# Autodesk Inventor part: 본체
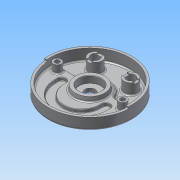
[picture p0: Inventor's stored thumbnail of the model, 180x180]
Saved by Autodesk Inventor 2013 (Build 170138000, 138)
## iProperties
Created: 2015-04
Part Number: 본체
Material: 알루미늄 6061
Document SubType Name: Modeling
Designer: Administrator
Density: 2.71 g/cm^3
Mass: 1041.28 g
Surface Area: 1018.25 cm^2
Volume: 384.235 cm^3
Author: Administrator
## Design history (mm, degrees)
sketch "스케치1"
  geometry: C1 r 95 at (0, 0); 1 further point
  constraints: 1 centre point, 1 coincident
  dimensions: "d0" = 190 diameter of C1
extrude "돌출1" new body sketch "스케치1" stored distance "d1" = 32; taper "d2" = 0 deg
sketch "스케치2"
  geometry: L1 (-90, 0)-(90, 0); L2 (-89.196, 12)-(89.196, 12); A1 r 42 centre (0, 0) between (40.249, 12) and (-40.249, 12); A2 r 90 centre (0, 0) between (89.196, 12) and (-89.196, 12); 3 further points
  constraints: 4 end point, 4 point on circle, 2 centre point, 2 coincident, 2 midpoint, 2 point on line, 1 horizontal, 1 parallel, 1 vertical alignment
  dimensions: "d4" = 12 distance between parallel lines of L2 L1; "d6" = 90 radius of A2; "d7" = 42 radius of A1; "d8" = 178.39282 distance of L2.start L2.end
extrude "돌출2" cut sketch "스케치2" distance "d9" = 25; taper "d10" = 0 deg
fillet "모깎기1" dims "d11" = 10
sketch "스케치3"
  geometry: C1 r 15 at (-40, 52); C2 r 15 at (40, 52); 1 further point
  constraints: 2 centre point
  dimensions: "d12" = 30 diameter of C1; "d13" = 40 horizontal distance of point (0, 0) C1.centre; "d14" = 52 vertical distance of point (0, 0) C1.centre; "d15" = 30 diameter of C2; "d16" = 40 horizontal distance of point (0, 0) C2.centre; "d17" = 52 vertical distance of point (0, 0) C2.centre
extrude "돌출3" join sketch "스케치3" distance "d18" = 25; taper "d19" = 0 deg
hole "구멍1" diameter "d22" = 20; stored, may be unused: countersink angle "d26" = 90 deg, drill point angle "d28" = 118 deg; dims "d20" = 10, "d21" = 10, "d23" = 6, "d24" = 4, "d25" = 2, "d27" = 8
hole "구멍2" diameter "d31" = 20; stored, may be unused: countersink angle "d35" = 90 deg, drill point angle "d37" = 118 deg; dims "d29" = 10, "d30" = 10, "d32" = 6, "d33" = 4, "d34" = 2, "d36" = 8
sketch "스케치4"
  geometry: L1 (-6, 16.431)-(6, 16.431); L2 (6, 16.431)-(6, -16.431); L3 (6, -16.431)-(-6, -16.431); L4 (-6, -16.431)-(-6, 16.431); C1 r 10 at (0, 0) reference; C2 r 15 at (0, 0) reference; 3 further points
  constraints: 8 end point, 2 midpoint, 2 parallel, 1 horizontal, 1 horizontal alignment, 1 perpendicular, 1 vertical alignment
  dimensions: "d38" = 12 distance of L1.start L1.end; "d40" = 32.86237 distance between parallel lines of L3 L1
extrude "돌출4" cut sketch "스케치4" distance "d41" = 3; taper "d42" = 0 deg
sketch "스케치5"
  geometry: L1 (-47.117, 12)-(-76.916, 12) reference; L2 (76.916, 12)-(47.117, 12) reference; L3 (-95, 0)-(95, 0); L4 (0, 0)-(94.638, -8.28); L5 (0, 0)-(-94.638, -8.28); A1 r 42 centre (0, 0) between (38.056, 17.769) and (-38.056, 17.769) reference; A2 r 10 centre (-47.117, 22) between (-47.117, 12) and (-38.056, 17.769) reference; A3 r 10 centre (-76.916, 22) between (-86.53, 24.75) and (-76.916, 12) reference; A4 r 90 centre (0, 0) between (86.53, 24.75) and (-86.53, 24.75) reference; A5 r 10 centre (76.916, 22) between (76.916, 12) and (86.53, 24.75) reference; A6 r 10 centre (47.117, 22) between (38.056, 17.769) and (47.117, 12) reference; A7 r 95 centre (0, 0) between (-95, 0) and (95, 0) reference; A8 r 95 centre (0, 0) between (-94.638, -8.28) and (94.638, -8.28); 2 further points
  constraints: 6 end point, 5 point on circle, 2 coincident, 1 centre point, 1 midpoint, 1 parallel, 2 other
  dimensions: "d44" = 5 deg angle of L3 L4; "d45" = 5 deg angle of L3 L5
extrude "돌출5" cut sketch "스케치5" distance "d46" = 5; taper "d47" = 0 deg
sketch "스케치7"
  geometry: L1 (0, 0)-(94.638, -8.28) reference; L2 (-94.638, -8.28)-(0, 0) reference; L3 (0, 0)-(94.638, -8.28) reference; L4 (-94.638, -8.28)-(0, 0) reference; L5 (-47.117, 12)-(-76.916, 12) reference; L6 (76.916, 12)-(47.117, 12) reference; A1 r 95 centre (0, 0) between (-94.638, -8.28) and (94.638, -8.28) reference; A2 r 95 centre (0, 0) between (94.638, -8.28) and (-94.638, -8.28) reference; A3 r 42 centre (0, 0) between (38.056, 17.769) and (-38.056, 17.769) reference; A4 r 10 centre (-47.117, 22) between (-47.117, 12) and (-38.056, 17.769) reference; A5 r 10 centre (-76.916, 22) between (-86.53, 24.75) and (-76.916, 12) reference; A6 r 90 centre (0, 0) between (86.53, 24.75) and (-86.53, 24.75) reference; A7 r 10 centre (76.916, 22) between (76.916, 12) and (86.53, 24.75) reference; A8 r 10 centre (47.117, 22) between (38.056, 17.769) and (47.117, 12) reference; A9 r 90 centre (0, 0) between (-86.53, 24.75) and (86.53, 24.75); 1 further point
  constraints: 4 point on circle, 1 centre point, 1 coincident, 1 concentric
extrude "돌출6" cut sketch "스케치7" distance "d48" = 18; taper "d49" = 0 deg
sketch "스케치8"
  geometry: C1 r 35 at (0, 0); 1 further point
  constraints: 1 centre point, 1 coincident
  dimensions: "d50" = 70 diameter of C1
extrude "돌출7" join sketch "스케치8" distance "d51" = 10; taper "d52" = 0 deg
feature "면 기울기1" dims angle "d53" = 10 deg
hole "구멍3" diameter "d56" = 50; stored, may be unused: countersink angle "d60" = 90 deg, drill point angle "d62" = 0 deg; dims "d54" = 10, "d55" = 10, "d57" = 6, "d58" = 4, "d59" = 2, "d61" = 15
hole "구멍4" diameter "d65" = 23; stored, may be unused: countersink angle "d69" = 90 deg, drill point angle "d71" = 0 deg; dims "d63" = 10, "d64" = 10, "d66" = 6, "d67" = 4, "d68" = 2, "d70" = 15
chamfer "모따기1" distance "d72" = 1; stored, may be unused: second distance "d73" = 2, angle "d74" = 45 deg
sketch "스케치9"
  geometry: C1 r 9 at (-74, 0); 1 further point
  constraints: 1 centre point, 1 horizontal alignment
  dimensions: "d75" = 18 diameter of C1; "d77" = 74 distance of point (0, 0) C1.centre
extrude "돌출8" join sketch "스케치9" stored distance "d78" = 10; taper "d79" = 0 deg
sketch "스케치10"
  geometry: C1 r 9 at (74, 0) reference; 1 further point
hole "구멍5" sketch "스케치10" at (74, 0) diameter "d80" = 11; stored, may be unused: countersink angle "d84" = 90 deg, drill point angle "d86" = 0 deg; dims "d81" = 6, "d82" = 18, "d83" = 11, "d85" = 15
sketch "스케치11" dims "d105" = 3
  geometry: L1 (-32.044, -19)-(32.044, -19); L2 (-59, -19)-(-59, -14); L3 (-41, -19)-(-41, -14); L4 (41, -19)-(41, -14); L5 (59, -19)-(59, -14); A1 r 59 centre (0, -19) between (-59, -19) and (59, -19); A2 r 41 centre (0, -19) between (-41, -19) and (41, -19); A3 r 9 centre (-50, -14) between (-41, -14) and (-59, -14); A4 r 9 centre (50, -14) between (59, -14) and (41, -14); 2 further points
  constraints: 10 end point, 8 point on circle, 6 tangent, 4 centre point, 3 parallel, 2 coincident, 1 horizontal, 1 midpoint, 1 point on line, 1 vertical alignment
  dimensions: "d87" = 19 distance from line of point (0, 0) L1; "d88" = 118 diameter of A1; "d89" = 82 diameter of A2; "d91" = 5 distance of L2.start L2.end; "d92" = 5 distance of L3.start L3.end; "d93" = 5 distance of L4.start L4.end; "d94" = 5 distance of L5.start L5.end
extrude "돌출9" cut sketch "스케치11" distance "d95" = 7; taper "d96" = 0 deg
fillet "모깎기2" dims "d97" = 1
chamfer "모따기2" distance "d98" = 1; stored, may be unused: second distance "d99" = 2, angle "d100" = 45 deg
fillet "모깎기3" dims "d101" = 5
fillet "모깎기4" dims "d102" = 3
fillet "모깎기5" dims "d103" = 3
fillet "모깎기6" dims "d104" = 3
fillet "모깎기7" dims "d105" = 3
sketch "스케치12"
  geometry: L1 (0, 0)-(0, -51); L2 (-36.062, -36.062)-(-50.912, -50.912); L3 (36.062, -36.062)-(50.912, -50.912); A1 r 72 centre (0, 0) between (-50.912, -50.912) and (50.912, -50.912); A2 r 51 centre (0, 0) between (-36.062, -36.062) and (36.062, -36.062); 1 further point
  constraints: 6 end point, 5 point on circle, 2 centre point, 2 coincident, 1 vertical
  dimensions: "d106" = 144 diameter of A1; "d107" = 102 diameter of A2; "d108" = 45 deg angle of L1 L2; "d109" = 45 deg angle of L1 L3; "d110" = 21 distance of L2.start L2.end; "d111" = 21 distance of L3.start L3.end
extrude "돌출10" join sketch "스케치12" distance "d112" = 5; taper "d113" = 0 deg
fillet "모깎기8" dims "d114" = 5
fillet "모깎기9" dims "d115" = 3
fillet "모깎기10" dims "d116" = 5
sketch "스케치13"
  geometry: C1 r 68 at (0, 0); 1 further point
  constraints: 1 centre point, 1 coincident, 1 other
  dimensions: "d117" = 136 diameter of C1
feature "엠보싱1" sketch "스케치13" dims "d0" = 190, "d118" = 0.5, "d119" = 0
fillet "모깎기11" dims "d120" = 0.3
chamfer "모따기3" distance "d121" = 1; stored, may be unused: second distance "d122" = 2, angle "d123" = 45 deg
sketch "스케치14"
  geometry: L1 (-20, 6)-(20, 6); L2 (20, 6)-(20, -6); L3 (20, -6)-(-20, -6); L4 (-20, -6)-(-20, 6); C1 r 10 at (0, 0) reference; 3 further points
  constraints: 8 end point, 2 midpoint, 2 parallel, 1 horizontal, 1 horizontal alignment, 1 perpendicular, 1 vertical alignment
  dimensions: "d124" = 12 distance of L1.end L2.end; "d127" = 40 distance between parallel lines of L2 L4
extrude "돌출11" cut sketch "스케치14" distance "d128" = 3; taper "d129" = 0 deg
node "솔리드1"
mirror "대칭2"
node "투영된 루프1"
node "투영된 루프2"
node "투영된 루프3"
node "투영된 루프4"
node "투영된 루프5"
other parameters: "d5" = 84
